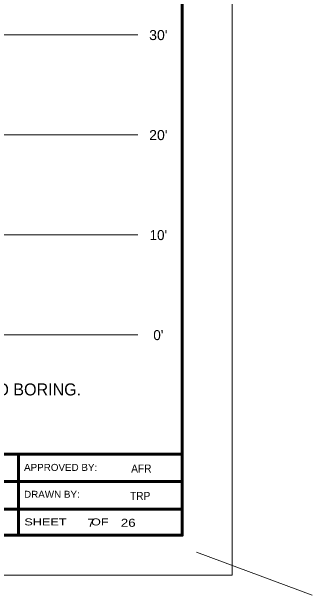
# Model space of a CAD drawing. Extents: x -76 to 974, y -1080 to -735.
# Drawn here: x 472.9 to 503, y -1058.1 to -999.8 of the extents above; entities that cross this region are included whole.
import ezdxf
from ezdxf.enums import TextEntityAlignment as Align

# ---------------------------------------------------------------- set-up
doc = ezdxf.new("R2010")
doc.units = 0
doc.header["$LTSCALE"] = 0.36
for name, color, linetype, lineweight in [('27', 7, 'Continuous', 40), ('63', 7, 'Continuous', 35), ('7', 7, 'Continuous', 13)]:
    doc.layers.add(name, color=color, linetype=linetype, lineweight=lineweight)
doc.layers.add('29', color=7, linetype='Continuous')

msp = doc.modelspace()

# ---------------------------------------------------------------- linework, layer by layer
at = {"layer": '27', "lineweight": 13}
msp.add_line((491.4081, -1053.8167), (502.9999, -1058.1254), dxfattribs=at)
at = {"layer": '63', "lineweight": 13}
for q in [(494.9866, -886.1123), (384.9866, -1056.1123)]:
    msp.add_line((494.9866, -1056.1123), q, dxfattribs=at)
at = {"layer": '63', "lineweight": 60}
for p, q in [((489.9866, -891.4595), (489.9866, -1052.1123)), ((473.6205, -1044.0258), (473.6205, -1052.1123)), ((457.2543, -1046.7337), (489.9866, -1046.7337)), ((457.2543, -1049.4971), (489.9866, -1049.4971))]:
    msp.add_line(p, q, dxfattribs=at)
at = {"layer": '63'}
msp.add_line((389.9866, -1052.1123), (489.9866, -1052.1123), dxfattribs=at)
at = {"layer": '63', "lineweight": 60}
msp.add_lwpolyline([(389.9866, -1044.0258), (489.9866, -1044.0258), (489.9866, -1052.1123), (389.9866, -1052.1123)], close=True, dxfattribs=at)
at = {"layer": '7'}
for p, q in [((466.7019, -1002.09), (485.5478, -1002.09)), ((401.4951, -1012.09), (485.5478, -1012.09)), ((401.4046, -1022.09), (485.5478, -1022.09)), ((401.4951, -1032.09), (485.5478, -1032.09))]:
    msp.add_line(p, q, dxfattribs=at)

# ---------------------------------------------------------------- texts
at = {"layer": '29'}
msp.add_text('NOTE: STRATIGRAPHY IS DRAWN FROM BORING TO BORING.', height=1.2, dxfattribs=at).set_placement((455.8078, -1038.137), align=Align.CENTER)
at = {"layer": '63'}
for s, height, width, p in [("30'", 1, 1.05, (487.601, -1002.6008)), ("20'", 1, 1.05, (487.601, -1012.6008)), ('AFR', 0.8, 0.95, (485.9044, -1045.8473)), ('TRP', 0.8, 0.95, (485.7818, -1048.5865)), ('7       26', 0.8, 1.25, (482.9175, -1051.2733))]:
    msp.add_text(s, height=height, dxfattribs=dict(at, width=width)).set_placement(p, align=Align.CENTER)
for s, p in [("10'", (487.601, -1022.6008)), ("0'", (487.6009, -1032.6008))]:
    msp.add_text(s, height=1, dxfattribs=at).set_placement(p, align=Align.CENTER)
for s, width, p in [('APPROVED BY:', 1.05, (474.1734, -1045.683)), ('DRAWN BY:', 1.05, (474.1734, -1048.372)), ('SHEET       OF', 1.35, (474.2044, -1051.135))]:
    msp.add_text(s, height=0.6999, dxfattribs=dict(at, width=width)).set_placement(p)

doc.saveas('drawing.dxf')
